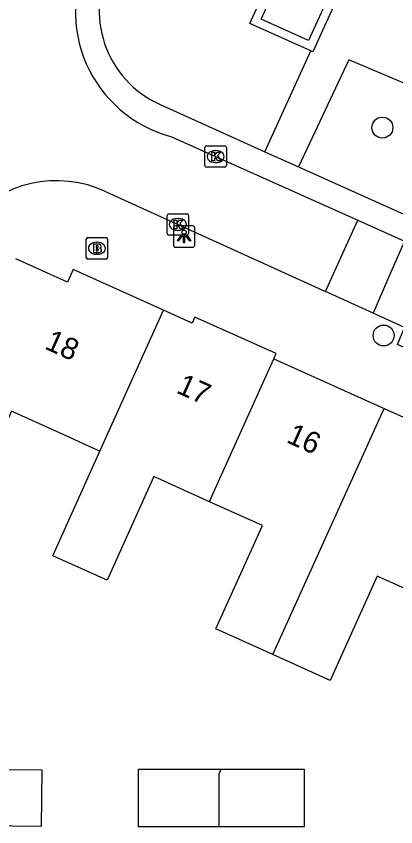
# Model space of a CAD drawing. Extents: x 161845 to 162341, y 381620 to 382158.
# Drawn here: x 162150.69 to 162168.42, y 381678.41 to 381716.3 of the extents above; entities that cross this region are included whole.
import ezdxf

# ---------------------------------------------------------------- set-up
doc = ezdxf.new("R2010")
doc.units = 0
for name, color, linetype in [('IMGEO_Boom', 7, 'Continuous'), ('IMGEO_Brandkraan', 7, 'Continuous'), ('IMGEO_Groenvoorziening', 7, 'Continuous'), ('IMGEO_Kolk', 7, 'Continuous'), ('IMGEO_Lichtpunt', 7, 'Continuous'), ('IMGEO_Pand', 7, 'Continuous'), ('IMGEO_Pand_nummerreeks', 7, 'Continuous'), ('IMGEO_Rijbaan_lokaal_open', 7, 'Continuous'), ('IMGEO_Voetpad_open', 7, 'Continuous')]:
    doc.layers.add(name, color=color, linetype=linetype)

msp = doc.modelspace()

# ---------------------------------------------------------------- linework, layer by layer
at = {"layer": 'IMGEO_Boom'}
for centre in [(162167.797, 381711.094), (162167.854, 381701.375)]:
    msp.add_circle(centre, 0.489, dxfattribs=at)
at = {"layer": 'IMGEO_Brandkraan'}
for p, q in [((162153.956, 381705.025), (162153.956, 381705.877)), ((162154.031, 381705.951), (162154.883, 381705.951)), ((162154.957, 381705.877), (162154.957, 381705.025)), ((162154.444, 381705.731), (162154.469, 381705.731)), ((162154.467, 381705.171), (162154.442, 381705.171)), ((162154.883, 381704.951), (162154.031, 381704.951))]:
    msp.add_line(p, q, dxfattribs=at)
for points in [[(162153.956, 381705.025), (162153.956, 381705.877)], [(162154.031, 381705.951), (162154.883, 381705.951)], [(162154.957, 381705.877), (162154.957, 381705.025)], [(162154.304, 381705.651), (162154.304, 381705.251), (162154.517, 381705.251)], [(162154.535, 381705.651), (162154.304, 381705.651)], [(162154.483, 381705.57), (162154.429, 381705.57), (162154.429, 381705.494)], [(162154.429, 381705.494), (162154.482, 381705.494)], [(162154.491, 381705.418), (162154.429, 381705.418), (162154.429, 381705.337)], [(162154.429, 381705.337), (162154.491, 381705.337)], [(162154.883, 381704.951), (162154.031, 381704.951)]]:
    msp.add_lwpolyline(points, dxfattribs=at)
for centre, radius, start, end in [((162154.033, 381705.875), 0.0765, 91.552, 178.448), ((162154.033, 381705.875), 0.0765, 91.552, 178.448), ((162154.881, 381705.875), 0.0765, 1.552, 88.448), ((162154.881, 381705.875), 0.0765, 1.552, 88.448), ((162154.484, 381705.532), 0.0379, 267.8285, 90.9355), ((162154.539, 381705.506), 0.145, 59.4692, 91.5367), ((162154.564, 381705.553), 0.0922, 285.5137, 58.1501), ((162154.569, 381705.361), 0.105, 301.3115, 78.989), ((162154.492, 381705.377), 0.0404, 269.8759, 90.5077), ((162154.523, 381705.502), 0.251, 268.6676, 293.5347), ((162154.033, 381705.027), 0.0765, 181.552, 268.448), ((162154.033, 381705.027), 0.0765, 181.552, 268.448), ((162154.881, 381705.027), 0.0765, 271.552, 358.448), ((162154.881, 381705.027), 0.0765, 271.552, 358.448)]:
    msp.add_arc(centre, radius, start, end, dxfattribs=at)
for centre, major_axis, ratio, start_param, end_param in [((162154.443, 381705.451), (-0.387, 0.002), 0.722429, 4.712389, 7.853982), ((162154.468, 381705.451), (-0.39, 0.002), 0.717154, 1.570796, 4.712389)]:
    msp.add_ellipse(centre, major_axis=major_axis, ratio=ratio, start_param=start_param, end_param=end_param, dxfattribs=at)
at = {"layer": 'IMGEO_Groenvoorziening'}
for points in [[(162162.303, 381709.968), (162164.446, 381714.686)], [(162169.768, 381712.761), (162166.231, 381714.263), (162163.877, 381709.26)]]:
    msp.add_lwpolyline(points, dxfattribs=at)
at = {"layer": 'IMGEO_Kolk'}
for p, q in [((162159.505, 381709.315), (162159.505, 381710.167)), ((162159.58, 381710.241), (162160.432, 381710.241)), ((162159.993, 381710.021), (162160.018, 381710.021)), ((162160.506, 381710.167), (162160.506, 381709.315)), ((162160.432, 381709.241), (162159.58, 381709.241)), ((162160.016, 381709.461), (162159.991, 381709.461)), ((162157.741, 381706.14), (162157.741, 381706.992)), ((162157.816, 381707.066), (162158.668, 381707.066)), ((162158.742, 381706.992), (162158.742, 381706.14)), ((162158.229, 381706.846), (162158.254, 381706.846)), ((162158.252, 381706.286), (162158.227, 381706.286)), ((162158.668, 381706.066), (162157.816, 381706.066))]:
    msp.add_line(p, q, dxfattribs=at)
for points in [[(162159.505, 381709.315), (162159.505, 381710.167)], [(162159.58, 381710.241), (162160.432, 381710.241)], [(162160.506, 381710.167), (162160.506, 381709.315)], [(162159.826, 381709.941), (162159.949, 381709.941), (162159.949, 381709.79), (162160.079, 381709.941), (162160.243, 381709.941), (162160.097, 381709.79), (162160.25, 381709.541), (162160.098, 381709.541), (162160.013, 381709.705), (162159.949, 381709.638), (162159.949, 381709.541), (162159.826, 381709.541), (162159.826, 381709.941)], [(162160.432, 381709.241), (162159.58, 381709.241)], [(162157.741, 381706.14), (162157.741, 381706.992)], [(162157.816, 381707.066), (162158.668, 381707.066)], [(162158.742, 381706.992), (162158.742, 381706.14)], [(162158.062, 381706.766), (162158.185, 381706.766), (162158.185, 381706.615), (162158.315, 381706.766), (162158.479, 381706.766), (162158.333, 381706.615), (162158.486, 381706.366), (162158.334, 381706.366), (162158.249, 381706.53), (162158.185, 381706.463), (162158.185, 381706.366), (162158.062, 381706.366), (162158.062, 381706.766)], [(162158.668, 381706.066), (162157.816, 381706.066)]]:
    msp.add_lwpolyline(points, dxfattribs=at)
for centre, start, end in [((162159.582, 381710.165), 91.552, 178.448), ((162159.582, 381710.165), 91.552, 178.448), ((162160.43, 381710.165), 1.552, 88.448), ((162160.43, 381710.165), 1.552, 88.448), ((162159.582, 381709.317), 181.552, 268.448), ((162159.582, 381709.317), 181.552, 268.448), ((162160.43, 381709.317), 271.552, 358.448), ((162160.43, 381709.317), 271.552, 358.448), ((162157.818, 381706.99), 91.552, 178.448), ((162157.818, 381706.99), 91.552, 178.448), ((162158.666, 381706.99), 1.552, 88.448), ((162158.666, 381706.99), 1.552, 88.448), ((162157.818, 381706.142), 181.552, 268.448), ((162157.818, 381706.142), 181.552, 268.448), ((162158.666, 381706.142), 271.552, 358.448), ((162158.666, 381706.142), 271.552, 358.448)]:
    msp.add_arc(centre, 0.0765, start, end, dxfattribs=at)
for centre, major_axis, ratio, start_param, end_param in [((162159.992, 381709.741), (-0.387, 0.002), 0.722429, 4.712389, 7.853982), ((162160.017, 381709.741), (-0.39, 0.002), 0.717154, 1.570796, 4.712389), ((162158.228, 381706.566), (-0.387, 0.002), 0.722429, 4.712389, 7.853982), ((162158.253, 381706.566), (-0.39, 0.002), 0.717154, 1.570796, 4.712389)]:
    msp.add_ellipse(centre, major_axis=major_axis, ratio=ratio, start_param=start_param, end_param=end_param, dxfattribs=at)
at = {"layer": 'IMGEO_Lichtpunt'}
for p, q in [((162158.033, 381706.406), (162158.033, 381705.599)), ((162158.033, 381706.406), (162158.033, 381705.599)), ((162158.935, 381706.501), (162158.127, 381706.501)), ((162158.935, 381706.501), (162158.127, 381706.501)), ((162159.029, 381705.599), (162159.029, 381706.406)), ((162159.029, 381705.599), (162159.029, 381706.406)), ((162158.127, 381705.505), (162158.935, 381705.505)), ((162158.127, 381705.505), (162158.935, 381705.505))]:
    msp.add_line(p, q, dxfattribs=at)
for points in [[(162158.407, 381706.07), (162158.446, 381706.042), (162158.258, 381705.78), (162158.22, 381705.807), (162158.407, 381706.07)], [(162158.509, 381706.022), (162158.556, 381706.022), (162158.556, 381705.7), (162158.509, 381705.7), (162158.509, 381706.022)], [(162158.619, 381706.042), (162158.657, 381706.069), (162158.844, 381705.807), (162158.805, 381705.779), (162158.619, 381706.042)]]:
    msp.add_lwpolyline(points, dxfattribs=at)
msp.add_circle((162158.532, 381706.204), 0.0994, dxfattribs=at)
for centre, start, end in [((162158.127, 381706.406), 90, 180), ((162158.127, 381706.406), 90, 180), ((162158.935, 381706.406), 0, 90), ((162158.935, 381706.406), 0, 90), ((162158.127, 381705.599), 180, 270), ((162158.127, 381705.599), 180, 270), ((162158.935, 381705.599), 270, 0), ((162158.935, 381705.599), 270, 360)]:
    msp.add_arc(centre, 0.0946, start, end, dxfattribs=at)
at = {"layer": 'IMGEO_Pand'}
for points in [[(162157.566, 381702.566), (162153.351, 381704.466), (162153.083, 381703.87), (162150.664, 381704.961)], [(162154.598, 381695.967), (162157.566, 381702.566)], [(162162.73, 381700.289), (162162.837, 381700.527), (162159.04, 381702.239), (162158.914, 381701.958), (162157.566, 381702.566)], [(162159.718, 381693.606), (162159.848, 381693.894), (162162.73, 381700.289)], [(162162.73, 381700.289), (162167.874, 381697.969)], [(162162.685, 381686.455), (162167.874, 381697.969)], [(162167.874, 381697.969), (162173.017, 381695.65)], [(162154.598, 381695.967), (162154.068, 381696.206), (162153.192, 381696.601), (162150.467, 381697.83), (162149.639, 381695.998), (162149.37, 381695.402), (162148.392, 381693.238), (162145.886, 381694.369)], [(162159.718, 381693.606), (162157.114, 381694.78), (162154.929, 381689.935), (162152.398, 381691.077), (162154.598, 381695.967)], [(162162.685, 381686.455), (162160.012, 381687.66), (162162.19, 381692.491), (162159.718, 381693.606)], [(162170.026, 381689.013), (162167.551, 381690.129), (162165.352, 381685.252), (162162.685, 381686.455)], [(162147.863, 381681.102), (162151.879, 381681.066), (162151.855, 381678.427), (162147.838, 381678.463)], [(162160.177, 381678.407), (162156.399, 381678.407), (162156.399, 381681.096), (162160.269, 381681.096)], [(162160.177, 381678.407), (162160.175, 381680.887), (162160.269, 381681.096)], [(162160.269, 381681.096), (162164.14, 381681.096), (162164.14, 381678.407), (162160.177, 381678.407)]]:
    msp.add_lwpolyline(points, dxfattribs=at)
at = {"layer": 'IMGEO_Rijbaan_lokaal_open'}
for points in [[(162157.91, 381710.677), (162166.642, 381706.769)], [(162154.893, 381708.09), (162165.139, 381703.432)], [(162165.139, 381703.432), (162165.947, 381705.227), (162166.642, 381706.769)], [(162166.642, 381706.769), (162168.827, 381705.791)], [(162168.827, 381705.791), (162168.089, 381704.089), (162167.365, 381702.42)], [(162167.365, 381702.42), (162165.139, 381703.432)], [(162192.206, 381691.211), (162190.876, 381691.811), (162190.513, 381691.034), (162168.498, 381700.961), (162168.836, 381701.751), (162167.365, 381702.42)]]:
    msp.add_lwpolyline(points, dxfattribs=at)
for centre, radius, start, end in [((162159.49, 381716.503), 6.037, 152.5617, 254.8311), ((162152.569, 381703.18), 5.432, 64.6686, 140.6826)]:
    msp.add_arc(centre, radius, start, end, dxfattribs=at)
at = {"layer": 'IMGEO_Voetpad_open'}
for points in [[(162164.446, 381714.686), (162161.608, 381715.968), (162162.942, 381718.922), (162165.884, 381717.592)], [(162165.355, 381717.392), (162164.35, 381715.168), (162162.137, 381716.168), (162163.142, 381718.392), (162165.355, 381717.392)], [(162165.884, 381717.592), (162164.55, 381714.639), (162164.446, 381714.686)], [(162157.379, 381712.184), (162162.303, 381709.968)], [(162162.303, 381709.968), (162163.877, 381709.26)], [(162163.877, 381709.26), (162168.826, 381707.033)]]:
    msp.add_lwpolyline(points, dxfattribs=at)
msp.add_arc((162159.375, 381716.563), 4.812, 151.9978, 245.4976, dxfattribs=at)

# ---------------------------------------------------------------- texts
at = {"layer": 'IMGEO_Pand_nummerreeks'}
for s, rotation, p in [('18', 335.7238, (162151.965, 381700.777)), ('17', 335.7467, (162158.121, 381698.718)), ('16', 335.7467, (162163.265, 381696.4))]:
    msp.add_text(s, height=1, rotation=rotation, dxfattribs=at).set_placement(p)

doc.saveas('drawing.dxf')
